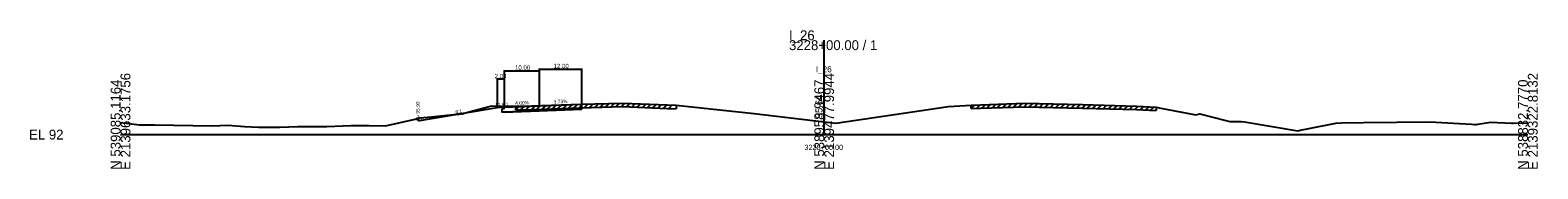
# Model space of a CAD drawing. Extents: x -13101 to 4803, y -924 to 22390.
# Drawn here: x 1974.3 to 2402.8, y 13990.3 to 14029.6 of the extents above; entities that cross this region are included whole.
import ezdxf

# ---------------------------------------------------------------- set-up
doc = ezdxf.new("R2010")
doc.units = 0
for name, color, linetype in [('RD_GPK_XS_Cell', 7, 'Continuous'), ('RD_XD_TX_Width', 7, 'Continuous'), ('RD_XS_Base', 7, 'Continuous'), ('RD_XS_EarthShd', 7, 'Continuous'), ('RD_XS_EwShp', 7, 'Continuous'), ('RD_XS_ExGround', 7, 'Continuous'), ('RD_XS_ExPaveRet', 7, 'Continuous'), ('RD_XS_OSBase', 7, 'Continuous'), ('RD_XS_Pave', 7, 'Continuous'), ('RD_XS_TieSlope', 7, 'Continuous'), ('RD_XS_TX_Baseline', 7, 'Continuous'), ('RD_XS_TX_Elev_EX', 7, 'Continuous'), ('RD_XS_TX_Elev_PR', 7, 'Continuous'), ('RD_XS_TX_ShdSlope', 7, 'Continuous'), ('RD_XS_TX_Slope', 7, 'Continuous'), ('RD_XS_TX_Station', 7, 'Continuous')]:
    doc.layers.add(name, color=color, linetype=linetype)

msp = doc.modelspace()

# ---------------------------------------------------------------- linework, layer by layer
at = {"layer": 'RD_GPK_XS_Cell'}
for p, q in [((2200, 14000), (2200, 14026.75)), ((2000, 14000), (2200, 14000)), ((2200, 14000), (2400, 14000))]:
    msp.add_line(p, q, dxfattribs=at)
at = {"layer": 'RD_XD_TX_Width'}
for p, q in [((2109, 14018.31), (2109, 14007.96)), ((2109, 14018.11), (2119, 14018.11)), ((2119, 14018.76), (2119, 14008.36)), ((2119, 14018.56), (2131, 14018.56)), ((2119, 14018.31), (2119, 14008.36)), ((2131, 14018.76), (2131, 14008.81)), ((2107, 14015.91), (2107, 14007.8)), ((2109, 14015.71), (2107, 14015.71)), ((2109, 14015.91), (2109, 14007.96))]:
    msp.add_line(p, q, dxfattribs=at)
at = {"layer": 'RD_XS_Base'}
for p, q in [((2109, 14006.36), (2119, 14006.76)), ((2119, 14006.76), (2131, 14007.21))]:
    msp.add_line(p, q, dxfattribs=at)
at = {"layer": 'RD_XS_EarthShd'}
msp.add_line((2109, 14007.76), (2107, 14007.6), dxfattribs=at)
at = {"layer": 'RD_XS_EwShp'}
for points in [[(2085.11, 14004.71), (2088.4, 14005.05), (2096.41, 14005.84), (2085, 14003.93), (2083.99, 14004.44)], [(2097.52, 14006.02), (2096.41, 14005.84), (2097.09, 14005.9)], [(2116.86, 14008.14), (2130.79, 14008.6), (2131, 14008.61), (2131, 14008.21), (2131, 14007.21), (2119, 14006.76), (2109, 14006.36), (2108.5, 14006.34), (2108.5, 14007.34), (2109, 14007.36), (2109, 14007.76), (2107, 14007.6), (2097.52, 14006.02), (2097.62, 14006.05), (2104.78, 14007.99), (2105.43, 14008.11), (2112.31, 14008.06)]]:
    msp.add_lwpolyline(points, close=True, dxfattribs=at)
at = {"layer": 'RD_XS_ExGround'}
msp.add_lwpolyline([(2000, 14003.41), (2003.23, 14003.04), (2005.26, 14002.76), (2009.65, 14002.72), (2026.06, 14002.48), (2030.63, 14002.63), (2035.27, 14002.26), (2039.25, 14002.12), (2041.06, 14002.15), (2045.3, 14002.09), (2050.43, 14002.29), (2058.62, 14002.32), (2065.5, 14002.53), (2070.65, 14002.53), (2075.29, 14002.44), (2083.75, 14004.38), (2085.11, 14004.71), (2088.4, 14005.05), (2097.09, 14005.9), (2097.62, 14006.05), (2104.78, 14007.99), (2105.43, 14008.11), (2112.31, 14008.06), (2116.86, 14008.14), (2130.79, 14008.6), (2142.78, 14008.92), (2155.41, 14008.44), (2157.95, 14008.34), (2180.14, 14005.97), (2200, 14003.64), (2203.33, 14003.26), (2235.35, 14008), (2241.79, 14008.35), (2244.39, 14008.48), (2256.95, 14008.9), (2269.12, 14008.61), (2273.46, 14008.5), (2288.72, 14008.1), (2294.36, 14007.8), (2295.69, 14007.52), (2305.59, 14005.58), (2306.8, 14005.93), (2314.14, 14003.98), (2315.33, 14003.72), (2317.67, 14003.73), (2318.53, 14003.71), (2319.46, 14003.59), (2334.66, 14001.1), (2335.29, 14001.23), (2337.26, 14001.6), (2345.4, 14003.27), (2347.04, 14003.37), (2353.27, 14003.38), (2372.12, 14003.61), (2383.94, 14002.94), (2384.87, 14002.89), (2385.41, 14002.87), (2385.8, 14002.94), (2389.37, 14003.54), (2395.42, 14003.26), (2395.89, 14003.27), (2400, 14003.29)], dxfattribs=at)
at = {"layer": 'RD_XS_ExPaveRet'}
for p, q in [((2134.81, 14007.71), (2135.84, 14008.73)), ((2136.31, 14007.75), (2137.34, 14008.77)), ((2137.81, 14007.79), (2138.84, 14008.81)), ((2139.31, 14007.82), (2140.34, 14008.85)), ((2140.81, 14007.86), (2141.84, 14008.89)), ((2142.31, 14007.9), (2143.3, 14008.9)), ((2143.81, 14007.88), (2144.77, 14008.84)), ((2145.31, 14007.82), (2146.27, 14008.78)), ((2252.29, 14007.74), (2253.32, 14008.78)), ((2253.79, 14007.8), (2254.82, 14008.83)), ((2255.29, 14007.85), (2256.32, 14008.88)), ((2256.79, 14007.9), (2257.77, 14008.88)), ((2258.29, 14007.87), (2259.26, 14008.85)), ((2259.79, 14007.83), (2260.76, 14008.81)), ((2261.29, 14007.8), (2262.26, 14008.77)), ((2262.79, 14007.76), (2263.76, 14008.74)), ((2112.31, 14007.06), (2113.33, 14008.08)), ((2112.31, 14007.06), (2112.31, 14008.06)), ((2112.31, 14007.06), (2116.86, 14007.14)), ((2113.81, 14007.09), (2114.83, 14008.1)), ((2115.31, 14007.11), (2116.33, 14008.13)), ((2116.81, 14007.14), (2117.84, 14008.17)), ((2116.86, 14007.14), (2130.79, 14007.6)), ((2118.31, 14007.19), (2119.35, 14008.22)), ((2119.81, 14007.24), (2120.85, 14008.27)), ((2121.31, 14007.29), (2122.35, 14008.32)), ((2122.81, 14007.34), (2123.85, 14008.37)), ((2124.31, 14007.39), (2125.35, 14008.42)), ((2125.81, 14007.44), (2126.85, 14008.47)), ((2127.31, 14007.49), (2128.35, 14008.52)), ((2128.81, 14007.54), (2129.85, 14008.57)), ((2130.31, 14007.59), (2131.34, 14008.62)), ((2130.79, 14007.6), (2142.78, 14007.92)), ((2131.81, 14007.63), (2132.84, 14008.66)), ((2133.31, 14007.67), (2134.34, 14008.7)), ((2142.78, 14007.92), (2155.41, 14007.44)), ((2146.81, 14007.76), (2147.77, 14008.73)), ((2148.31, 14007.71), (2149.27, 14008.67)), ((2149.81, 14007.65), (2150.77, 14008.61)), ((2151.31, 14007.59), (2152.27, 14008.56)), ((2152.81, 14007.54), (2153.77, 14008.5)), ((2154.31, 14007.48), (2155.27, 14008.44)), ((2155.41, 14007.44), (2157.95, 14007.34)), ((2155.81, 14007.42), (2156.78, 14008.39)), ((2157.95, 14008.34), (2157.95, 14007.34)), ((2241.79, 14007.35), (2242.84, 14008.4)), ((2241.79, 14007.35), (2241.79, 14008.35)), ((2241.79, 14007.35), (2244.39, 14007.48)), ((2243.29, 14007.43), (2244.34, 14008.47)), ((2244.39, 14007.48), (2256.95, 14007.9)), ((2244.79, 14007.49), (2245.82, 14008.53)), ((2246.29, 14007.54), (2247.32, 14008.58)), ((2247.79, 14007.59), (2248.82, 14008.63)), ((2249.29, 14007.64), (2250.32, 14008.68)), ((2250.79, 14007.69), (2251.82, 14008.73)), ((2256.95, 14007.9), (2269.12, 14007.61)), ((2264.29, 14007.72), (2265.26, 14008.7)), ((2265.79, 14007.69), (2266.76, 14008.66)), ((2267.29, 14007.65), (2268.26, 14008.63)), ((2268.79, 14007.62), (2269.76, 14008.59)), ((2269.12, 14007.61), (2273.46, 14007.5)), ((2270.29, 14007.58), (2271.26, 14008.55)), ((2271.79, 14007.54), (2272.76, 14008.51)), ((2273.29, 14007.5), (2274.26, 14008.47)), ((2273.46, 14007.5), (2288.72, 14007.1)), ((2274.79, 14007.46), (2275.76, 14008.44)), ((2276.29, 14007.42), (2277.26, 14008.4)), ((2277.79, 14007.38), (2278.76, 14008.36)), ((2279.29, 14007.34), (2280.26, 14008.32)), ((2280.79, 14007.3), (2281.76, 14008.28)), ((2282.29, 14007.27), (2283.26, 14008.24)), ((2283.79, 14007.23), (2284.76, 14008.2)), ((2285.29, 14007.19), (2286.26, 14008.16)), ((2286.79, 14007.15), (2287.76, 14008.12)), ((2288.29, 14007.11), (2289.25, 14008.07)), ((2288.72, 14007.1), (2294.36, 14006.8)), ((2289.79, 14007.04), (2290.74, 14007.99)), ((2291.29, 14006.96), (2292.24, 14007.91)), ((2292.79, 14006.88), (2293.74, 14007.83)), ((2294.36, 14007.8), (2294.36, 14006.8))]:
    msp.add_line(p, q, dxfattribs=at)
at = {"layer": 'RD_XS_OSBase'}
for p, q in [((2108.5, 14007.34), (2109, 14007.36)), ((2108.5, 14006.34), (2108.5, 14007.34)), ((2109, 14006.36), (2108.5, 14006.34)), ((2109, 14007.36), (2109, 14007.76)), ((2131, 14008.21), (2131, 14008.61)), ((2131, 14007.21), (2131, 14008.21))]:
    msp.add_line(p, q, dxfattribs=at)
at = {"layer": 'RD_XS_Pave'}
for p, q in [((2109, 14007.76), (2119, 14008.16)), ((2119, 14008.16), (2131, 14008.61))]:
    msp.add_line(p, q, dxfattribs=at)
at = {"layer": 'RD_XS_TieSlope'}
for p, q in [((2107, 14007.6), (2085, 14003.93)), ((2085, 14003.93), (2083.99, 14004.44))]:
    msp.add_line(p, q, dxfattribs=at)

# ---------------------------------------------------------------- texts
at = {"layer": 'RD_GPK_XS_Cell'}
for s, p in [('3228+00.00 / 1', (2190, 14023.95)), ('I_26', (2190, 14026.75)), ('EL 92', (1974, 13998.6))]:
    msp.add_text(s, height=2.8, dxfattribs=at).set_placement(p)
for s, p in [('E 2139633.1756', (2002.8, 13990)), ('E 2139477.9944', (2202.8, 13990)), ('N 539085.1164', (2000, 13990)), ('N 538958.9467', (2200, 13990)), ('N 538832.7770', (2400, 13990)), ('E 2139322.8132', (2402.8, 13990))]:
    msp.add_text(s, height=2.8, rotation=90, dxfattribs=at).set_placement(p)
at = {"layer": 'RD_XD_TX_Width'}
for s, p in [('10.00', (2112.11, 14018.36)), ('12.00', (2123.07, 14018.81)), ('2.00', (2106.31, 14015.96))]:
    msp.add_text(s, height=1.25, dxfattribs=at).set_placement(p)
at = {"layer": 'RD_XS_TX_Baseline'}
msp.add_text('I_26', height=1.75, dxfattribs=at).set_placement((2197.6, 14017.64))
at = {"layer": 'RD_XS_TX_Elev_EX'}
msp.add_text('95.64', height=2, rotation=90, dxfattribs=at).set_placement((2199.5, 14004.64))
at = {"layer": 'RD_XS_TX_Elev_PR'}
msp.add_text('95.93', height=1, rotation=90, dxfattribs=at).set_placement((2085, 14005.93))
at = {"layer": 'RD_XS_TX_ShdSlope'}
msp.add_text('12.5:1', height=1, rotation=4.5739, dxfattribs=at).set_placement((2106.47, 14007.81))
msp.add_text('12.5:1', height=1, rotation=4.5739, dxfattribs=at).set_placement((2106.47, 14007.81))
at = {"layer": 'RD_XS_TX_Slope'}
for s, rotation, p in [('4.00%', 2.2906, (2112.18, 14008.39)), ('3.73%', 2.1353, (2123.13, 14008.81)), ('2:1', 333.4349, (2083.93, 14004.75)), ('6:1', 9.4623, (2095.26, 14005.9))]:
    msp.add_text(s, height=1, rotation=rotation, dxfattribs=at).set_placement(p)
at = {"layer": 'RD_XS_TX_Station'}
msp.add_text('3228+00.00', height=1.5, dxfattribs=at).set_placement((2194.38, 13995.64))

doc.saveas('drawing.dxf')
